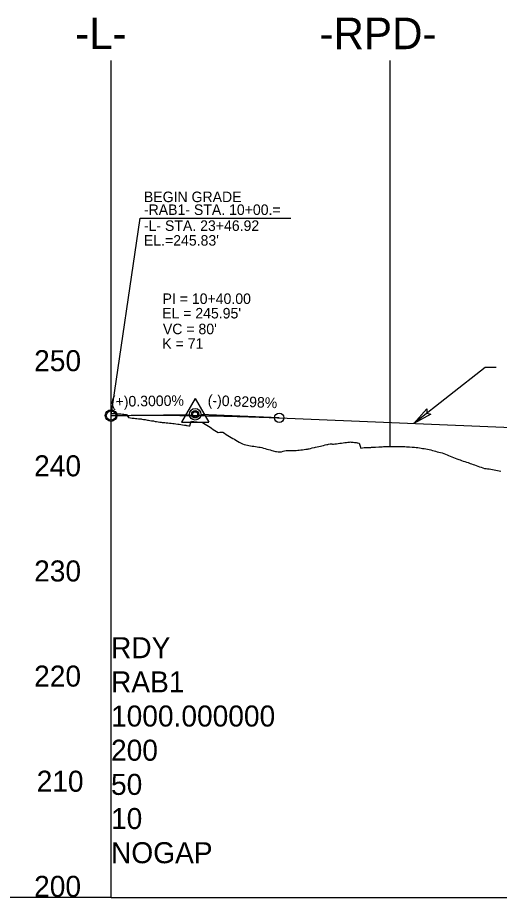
# Model space of a CAD drawing. Extents: x 2115752 to 2121174, y 562881 to 567245.
# Drawn here: x 2120077.9 to 2120307, y 565506.4 to 565924.8 of the extents above; entities that cross this region are included whole.
import ezdxf

# ---------------------------------------------------------------- set-up
doc = ezdxf.new("R2010")
doc.units = 0
for name, color, linetype in [('Exist Profile Cell', 7, 'Continuous'), ('Exist Vertical Profile Ground Line', 7, 'Continuous'), ('Exist Vertical Profile Vertical Axis Label', 7, 'Continuous'), ('Prop PFL VPI Symbol CELL', 7, 'Continuous'), ('Prop Terminator CELL', 7, 'Continuous'), ('Prop Vertical Profile Curve Label', 7, 'Continuous'), ('Prop Vertical Profile Grade', 7, 'Continuous'), ('Prop Vertical Profile Grade Label', 7, 'Continuous'), ('Prop VPI Label', 7, 'Continuous'), ('Scratch_Level_1', 7, 'Continuous')]:
    doc.layers.add(name, color=color, linetype=linetype)

msp = doc.modelspace()

# ---------------------------------------------------------------- linework, layer by layer
at = {"layer": 'Exist Profile Cell'}
for q in [(2120122.31, 565756.42), (2120593.55, 565506.42), (2120122.31, 565506.42)]:
    msp.add_line((2120122.31, 565506.42), q, dxfattribs=at)
at = {"layer": 'Exist Vertical Profile Ground Line'}
for points in [[(2120122.31, 565736.54), (2120123.18, 565736.59), (2120123.85, 565736.54), (2120124.62, 565736.49), (2120125.4, 565736.43), (2120126.17, 565736.38), (2120126.53, 565736.35), (2120126.94, 565736.32), (2120127.71, 565736.26), (2120128.48, 565736.2), (2120129.25, 565736.13), (2120129.6, 565736.11), (2120130.62, 565734.68), (2120131.57, 565734.52), (2120132.34, 565734.41), (2120133.36, 565734.27), (2120133.89, 565734.18), (2120134.2, 565734.14), (2120134.66, 565734.11), (2120135.43, 565734.06), (2120136.2, 565734.01), (2120136.6, 565733.98), (2120136.97, 565733.91), (2120137.74, 565733.77), (2120138.52, 565733.62), (2120139.72, 565733.4), (2120140.06, 565733.35), (2120140.83, 565733.23), (2120141.6, 565733.12), (2120142.45, 565732.99), (2120143.29, 565732.78), (2120143.92, 565732.7), (2120144.69, 565732.6), (2120145.46, 565732.49), (2120145.86, 565732.44), (2120146.23, 565732.39), (2120146.61, 565732.34), (2120147.01, 565732.31), (2120147.93, 565732.23), (2120148.55, 565732.17), (2120148.88, 565732.15), (2120149.32, 565732.1), (2120150.16, 565732), (2120150.87, 565731.93), (2120151.67, 565731.85), (2120152.09, 565731.79), (2120152.41, 565731.75), (2120153.18, 565731.65), (2120154.04, 565731.54), (2120154.72, 565731.43), (2120155.5, 565731.32), (2120156.27, 565731.2), (2120157.3, 565731.04), (2120157.81, 565730.96), (2120158.16, 565730.88), (2120158.58, 565730.78), (2120159.35, 565730.61), (2120159.74, 565730.68), (2120160.41, 565732.83), (2120160.92, 565732.78), (2120161.67, 565732.71), (2120162.44, 565732.63), (2120163.21, 565732.56), (2120164.1, 565732.48), (2120164.76, 565732.42), (2120165.76, 565732.32), (2120166.3, 565731.98), (2120167.07, 565731.48), (2120167.84, 565730.99), (2120168.62, 565730.49), (2120169.39, 565730), (2120170.16, 565729.5), (2120170.93, 565729), (2120171.7, 565728.5), (2120172.48, 565728), (2120173.25, 565727.58), (2120174.02, 565727.63), (2120174.79, 565727.7), (2120175.56, 565727.61), (2120176.33, 565727.12), (2120177.11, 565726.63), (2120177.88, 565726.15), (2120178.65, 565725.67), (2120179.42, 565725.2), (2120180.19, 565724.74), (2120180.97, 565724.28), (2120181.74, 565723.82), (2120182.51, 565723.37), (2120183.28, 565722.93), (2120184.17, 565722.43), (2120184.82, 565722.13), (2120185.6, 565721.82), (2120186.37, 565721.66), (2120187.14, 565721.5), (2120187.91, 565721.35), (2120188.68, 565721.21), (2120189.45, 565721.08), (2120190.23, 565720.95), (2120191, 565720.83), (2120191.77, 565720.71), (2120192.54, 565720.61)], [(2120192.54, 565720.61), (2120193.31, 565720.51), (2120194.09, 565720.41), (2120194.86, 565720.14), (2120195.63, 565719.88), (2120196.4, 565719.66), (2120197.17, 565719.44), (2120197.94, 565719.22), (2120198.72, 565719.01), (2120199.49, 565718.81), (2120200.51, 565718.55), (2120201.03, 565718.48), (2120201.8, 565718.38), (2120202.77, 565718.27), (2120203.35, 565718.4), (2120204.12, 565718.58), (2120204.89, 565718.76), (2120205.66, 565718.93), (2120206.43, 565718.93), (2120207.21, 565718.94), (2120207.98, 565718.95), (2120208.75, 565718.97), (2120209.52, 565718.99), (2120210.29, 565719.02), (2120211.23, 565719.06), (2120211.84, 565719.13), (2120212.61, 565719.23), (2120213.38, 565719.33), (2120214.15, 565719.44), (2120214.92, 565719.55), (2120215.7, 565719.66), (2120216.03, 565719.72), (2120216.47, 565719.81), (2120217.24, 565719.98), (2120218.01, 565720.16), (2120219.01, 565720.4), (2120219.56, 565720.51), (2120220.33, 565720.68), (2120221.1, 565720.85), (2120221.87, 565721.02), (2120222.64, 565721.2), (2120223.41, 565721.39), (2120224.19, 565721.58), (2120224.96, 565721.77), (2120225.38, 565721.88), (2120225.73, 565721.94), (2120226.5, 565722.07), (2120227.27, 565722.05), (2120227.58, 565721.99), (2120228.04, 565722), (2120228.82, 565722.1), (2120229.59, 565722.2), (2120230.36, 565722.29), (2120231.13, 565722.39), (2120231.9, 565722.49), (2120232.68, 565722.59), (2120233.45, 565722.69), (2120234.22, 565722.78), (2120234.99, 565722.88), (2120235.76, 565722.98), (2120236.21, 565723.04), (2120236.53, 565722.99), (2120237.48, 565722.86), (2120238.08, 565722.79), (2120238.85, 565722.69), (2120239.31, 565722.64), (2120239.62, 565722.6), (2120240.39, 565722.39), (2120241.07, 565720.06), (2120241.94, 565720.2), (2120242.71, 565720.33), (2120243.48, 565720.38), (2120243.92, 565720.37), (2120244.25, 565720.39), (2120245.02, 565720.42), (2120245.8, 565720.45), (2120246.18, 565720.48), (2120246.57, 565720.51), (2120247.34, 565720.56), (2120248.11, 565720.61), (2120249.71, 565720.71), (2120250.43, 565720.73), (2120251.23, 565720.76), (2120251.97, 565720.79), (2120252.99, 565720.82), (2120253.51, 565720.83), (2120254.29, 565720.85), (2120255.06, 565720.87), (2120255.84, 565720.89), (2120256.6, 565720.89), (2120257.46, 565720.9), (2120258.15, 565720.89), (2120258.96, 565720.88), (2120259.7, 565720.85), (2120260.47, 565720.83), (2120261.24, 565720.8), (2120262.01, 565720.78), (2120262.79, 565720.73), (2120263.56, 565720.69), (2120264.33, 565720.65), (2120265.54, 565720.6)], [(2120265.54, 565720.6), (2120265.97, 565720.56), (2120266.65, 565720.5), (2120267.42, 565720.43), (2120267.86, 565720.39), (2120268.2, 565720.34), (2120268.97, 565720.23), (2120269.74, 565720.09), (2120270.52, 565719.98), (2120271.29, 565719.87), (2120272.06, 565719.76), (2120272.84, 565719.62), (2120273.61, 565719.41), (2120274.38, 565719.2), (2120275.15, 565719), (2120275.93, 565718.8), (2120276.7, 565718.6), (2120277.47, 565718.4), (2120278.25, 565718.21), (2120279.02, 565718.02), (2120279.79, 565717.8), (2120280.56, 565717.48), (2120281.34, 565717.16), (2120282.11, 565716.85), (2120282.88, 565716.53), (2120283.66, 565716.22), (2120284.43, 565715.91), (2120285.2, 565715.61), (2120285.97, 565715.31), (2120286.75, 565715.04), (2120287.76, 565714.67), (2120288.29, 565714.48), (2120289.07, 565714.21), (2120289.84, 565713.95), (2120290.61, 565713.69), (2120291.39, 565713.44), (2120292.16, 565713.18), (2120293.19, 565712.85), (2120293.7, 565712.66), (2120294.48, 565712.37), (2120295.25, 565712.08), (2120296.02, 565711.8), (2120296.8, 565711.53), (2120297.57, 565711.25), (2120298.34, 565710.98), (2120299.11, 565710.72), (2120299.89, 565710.46), (2120300.2, 565710.35), (2120300.66, 565710.32), (2120301.43, 565710.27), (2120302.22, 565710.22), (2120302.98, 565710.04), (2120303.75, 565709.87), (2120304.53, 565709.7), (2120305.3, 565709.53), (2120306.07, 565709.37), (2120306.84, 565709.22), (2120307.62, 565709.07)]]:
    msp.add_lwpolyline(points, dxfattribs=at)
at = {"layer": 'Prop PFL VPI Symbol CELL'}
for p, q in [((2120162.3, 565743.65), (2120155.85, 565732.45)), ((2120162.3, 565743.65), (2120168.8, 565732.45)), ((2120155.85, 565732.45), (2120168.8, 565732.45))]:
    msp.add_line(p, q, dxfattribs=at)
for radius in [1.75, 1.2]:
    msp.add_circle((2120162.31, 565736.17), radius, dxfattribs=at)
at = {"layer": 'Prop Terminator CELL'}
msp.add_lwpolyline([(2120274.33, 565736.19), (2120266.3, 565731.85), (2120272.43, 565738.7), (2120272.51, 565736.73)], close=True, dxfattribs=at)
at = {"layer": 'Prop Vertical Profile Curve Label'}
for centre in [(2120122.31, 565735.57), (2120202.31, 565734.51)]:
    msp.add_circle(centre, 2.25, dxfattribs=at)
at = {"layer": 'Prop Vertical Profile Grade'}
msp.add_line((2120202.31, 565734.51), (2120397.55, 565726.4), dxfattribs=at)
msp.add_spline([(2120122.31, 565735.57), (2120123.91, 565735.59), (2120125.51, 565735.61), (2120127.11, 565735.63), (2120128.71, 565735.65), (2120130.31, 565735.66), (2120131.91, 565735.68), (2120133.51, 565735.69), (2120135.11, 565735.7), (2120136.71, 565735.71), (2120138.31, 565735.71), (2120139.91, 565735.72), (2120141.51, 565735.72), (2120143.11, 565735.72), (2120144.71, 565735.72), (2120146.31, 565735.72), (2120147.91, 565735.72), (2120149.51, 565735.71), (2120151.11, 565735.7), (2120152.71, 565735.69), (2120154.31, 565735.68), (2120155.91, 565735.67), (2120157.51, 565735.66), (2120159.11, 565735.64), (2120160.71, 565735.62), (2120162.31, 565735.6), (2120163.91, 565735.58), (2120165.51, 565735.55), (2120167.11, 565735.53), (2120168.71, 565735.5), (2120170.31, 565735.47), (2120171.91, 565735.44), (2120173.51, 565735.41), (2120175.11, 565735.37), (2120176.71, 565735.34), (2120178.31, 565735.3), (2120179.91, 565735.26), (2120181.51, 565735.22), (2120183.11, 565735.17), (2120184.71, 565735.13), (2120186.31, 565735.08), (2120187.91, 565735.03), (2120189.51, 565734.98), (2120191.11, 565734.93), (2120192.71, 565734.87), (2120194.31, 565734.81), (2120195.91, 565734.76), (2120197.51, 565734.7), (2120199.11, 565734.63), (2120200.71, 565734.57), (2120202.31, 565734.51)], degree=3, dxfattribs=at)
at = {"layer": 'Prop VPI Label'}
for p, q in [((2120122.31, 565735.57), (2120136.18, 565829.37)), ((2120136.18, 565829.37), (2120207.8, 565829.37)), ((2120122.31, 565735.57), (2120159.56, 565736.12)), ((2120202.31, 565734.51), (2120165.06, 565736.05))]:
    msp.add_line(p, q, dxfattribs=at)
msp.add_lwpolyline([(2120305.53, 565758.48), (2120300.23, 565758.48), (2120266.3, 565731.85)], dxfattribs=at)
for centre in [(2120122.31, 565735.57), (2120162.31, 565736.17)]:
    msp.add_circle(centre, 2.75, dxfattribs=at)
at = {"layer": 'Scratch_Level_1'}
for p, q in [((2120122.31, 565506.42), (2120122.31, 565904.4)), ((2120255.06, 565720.88), (2120255.06, 565904.4)), ((2120122.31, 565506.42), (2119746.02, 565506.42))]:
    msp.add_line(p, q, dxfattribs=at)

# ---------------------------------------------------------------- texts
at = {"layer": 'Exist Profile Cell'}
for s, p in [('RDY', (2120122.31, 565620.17)), ('RAB1', (2120122.31, 565603.92)), ('1000.000000', (2120122.31, 565587.67)), ('200', (2120122.31, 565571.42)), ('50', (2120122.31, 565555.17)), ('10', (2120122.31, 565538.92)), ('NOGAP', (2120122.31, 565522.67))]:
    msp.add_text(s, height=10, dxfattribs=at).set_placement(p)
at = {"layer": 'Exist Vertical Profile Vertical Axis Label'}
for s, p in [('250', (2120085.74, 565756.67)), ('240', (2120085.74, 565706.67)), ('230', (2120085.74, 565656.67)), ('220', (2120085.74, 565606.67)), ('210', (2120086.94, 565556.67)), ('200', (2120085.74, 565506.67))]:
    msp.add_text(s, height=10, dxfattribs=at).set_placement(p)
at = {"layer": 'Prop Vertical Profile Curve Label'}
for s, p in [("VC = 80'", (2120146.99, 565774.26)), ('K = 71', (2120146.71, 565767.31))]:
    msp.add_text(s, height=5, dxfattribs=at).set_placement(p)
at = {"layer": 'Prop Vertical Profile Grade Label'}
for s, rotation, p in [('(+)0.3000%', 0.8594, (2120122.27, 565739.74)), ('(-)0.8298%', 357.6241, (2120168.22, 565740.42))]:
    msp.add_text(s, height=5, rotation=rotation, dxfattribs=at).set_placement(p)
at = {"layer": 'Prop VPI Label'}
for s, p in [('BEGIN GRADE', (2120137.95, 565837.08)), ('-RAB1- STA. 10+00.=', (2120137.95, 565830.98)), ('-L- STA. 23+46.92', (2120137.95, 565823.39)), ("EL.=245.83'", (2120137.95, 565816.39)), ('PI = 10+40.00', (2120146.83, 565788.65)), ("EL = 245.95'", (2120146.61, 565781.75))]:
    msp.add_text(s, height=5, dxfattribs=at).set_placement(p)
at = {"layer": 'Scratch_Level_1'}
for s, p in [('-L-', (2120105.22, 565909.84)), ('-RPD-', (2120221.43, 565909.82))]:
    msp.add_text(s, height=15, dxfattribs=at).set_placement(p)

doc.saveas('drawing.dxf')
